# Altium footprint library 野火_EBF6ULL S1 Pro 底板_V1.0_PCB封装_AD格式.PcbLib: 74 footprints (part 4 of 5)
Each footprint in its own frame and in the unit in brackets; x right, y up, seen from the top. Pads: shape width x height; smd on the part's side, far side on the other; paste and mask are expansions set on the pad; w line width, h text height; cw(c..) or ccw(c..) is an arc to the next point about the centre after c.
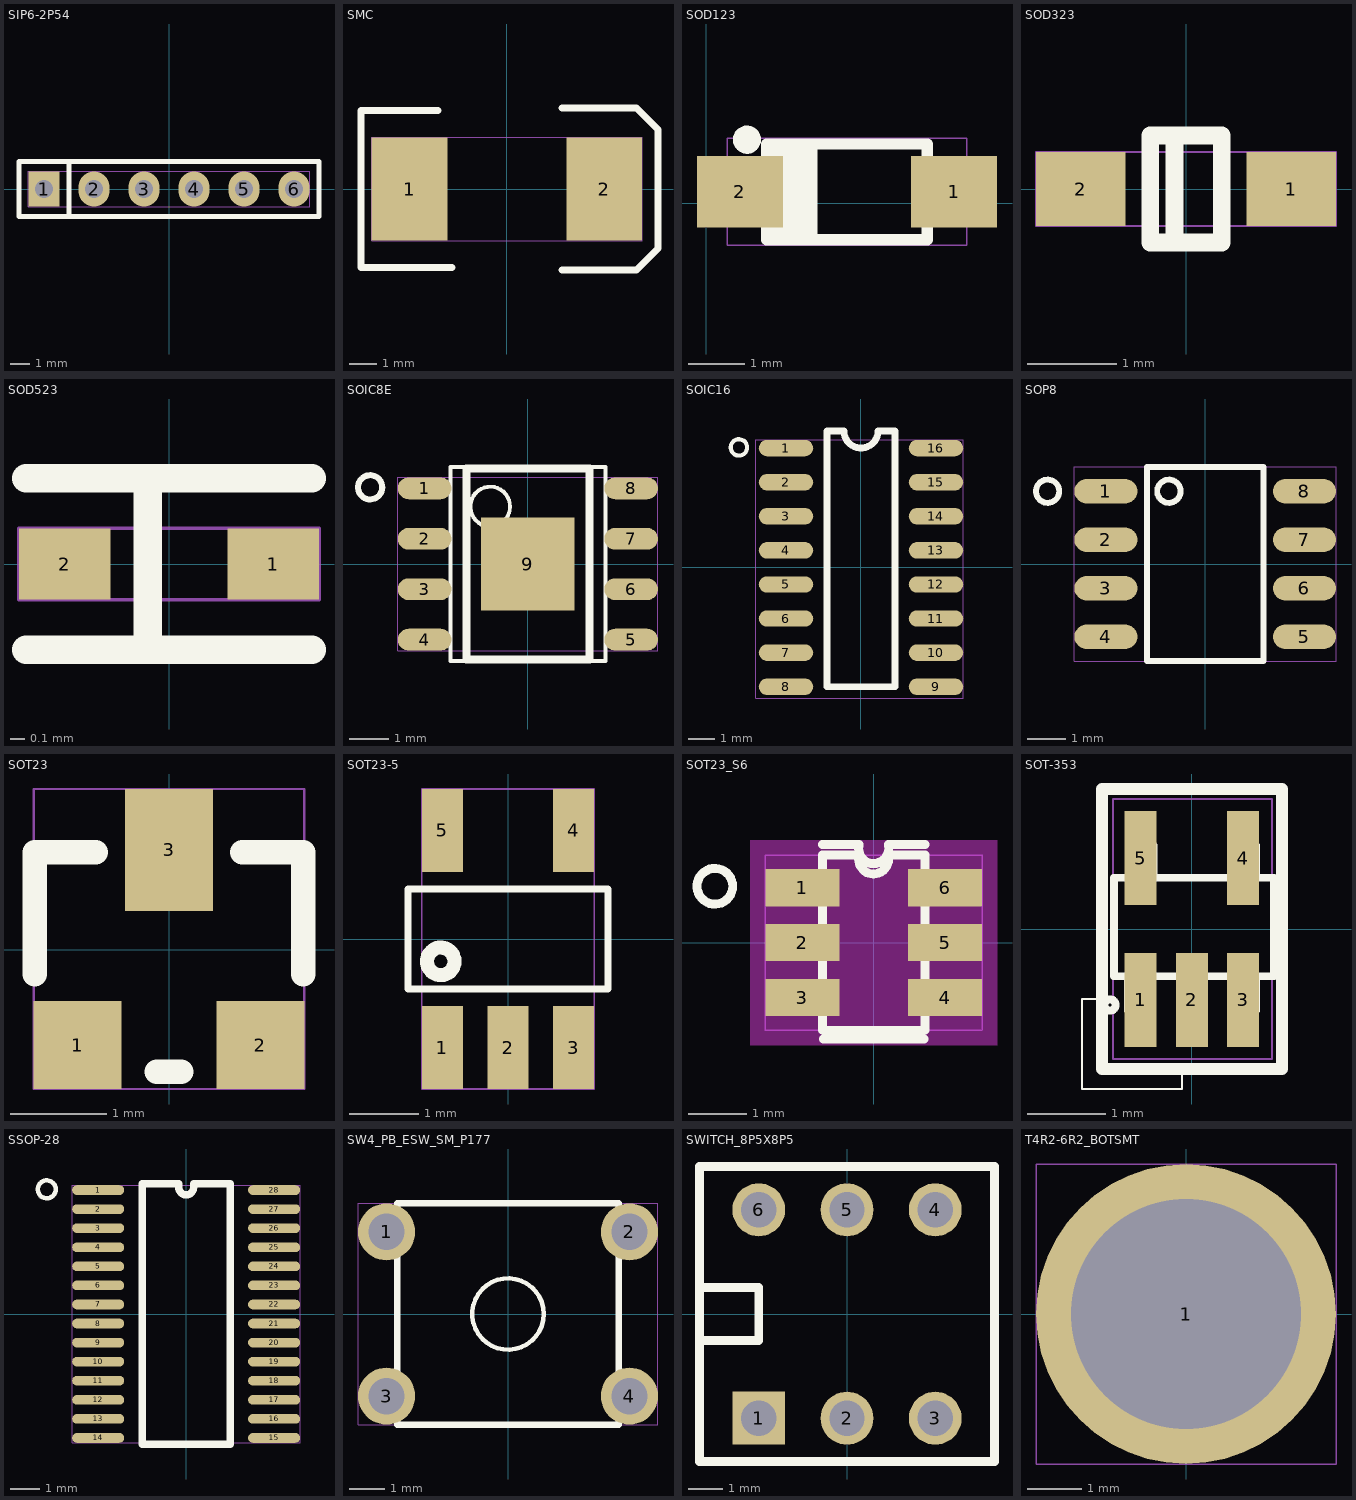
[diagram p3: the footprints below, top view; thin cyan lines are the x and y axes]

## SIP6-2P54 [mil]
pads (6):
  rect 62.99x70.87 hole 35.43 mask+1.97: 1(-250,0)
  oval 62.99x70.87 hole 35.43 mask+1.97: 2(-150,0) 3(-50,0) 4(50,0) 5(150,0) 6(250,0)
Top Overlay:
  lines w10: -200,-55.12 -200,55.12 ; -300,-55.12 -300,55.12 300,55.12 300,-55.12 -300,-55.12
Top Assembly:
  text "J15" at 53.33,25 h50
Mechanical 20:
  lines w1: -281.5,-35.43 -281.5,35.43 281.5,35.43 281.5,-35.43 -281.5,-35.43

## SMC [mil]
pads (2):
  rect 110.24x150 smd mask+1.97: 1(-141.73,0) 2(141.73,0)
Top Overlay:
  lines w10: -100,114.17 -212.6,114.17 -212.6,-114.17 -80,-114.17 ; 80,-118.11 188.5,-118.11 220,-86.61 220,86.61 188.5,118.11 80,118.11
Top Assembly:
  text "D3" at -38.93,-25 h50
Mechanical 20:
  lines w1: -196.85,-75 196.85,-75 196.85,75 -196.85,75 -196.85,-75

## SOD123 [mil]
height 53
pads (2):
  rect 60x50 smd mask+5: 1(173.23,7.87) 2(23.62,7.87)
Top Overlay:
  circle w9.84: c28.54,44.29 r4.92
  lines w7.87: 46.26,-25.59 46.26,41.34 ; 50.2,-25.59 50.2,41.34 ; 54.13,-25.59 54.13,41.34 ; 58.07,-25.59 58.07,41.34 ; 62.01,-25.59 62.01,41.34 ; 65.94,-25.59 65.94,41.34 ; 73.82,-25.59 73.82,41.34 ; 42.32,-25.59 42.32,41.34 ; 42.32,-25.59 154.53,-25.59 ; 42.32,-25.59 42.32,41.34 ; 42.32,-25.59 154.53,-25.59 ; 42.32,41.34 154.53,41.34 ; 42.32,41.34 154.53,41.34 ; 154.53,-25.59 154.53,41.34 ; 154.53,-25.59 154.53,41.34 ; 22.64,-0.98 22.64,16.73 38.39,16.73 38.39,-0.98 22.64,-0.98 ; 158.46,-0.98 158.46,16.73 174.21,16.73 174.21,-0.98 158.46,-0.98
Top Assembly:
  text "D12" at 57.25,25 h50
Mechanical 20:
  lines w1: 14.76,-29.53 182.09,-29.53 182.09,45.28 14.76,45.28 14.76,-29.53

## SOD323 [mm]
pads (2):
  rect 1x0.83 smd mask+0.05: 1(1.18,0) 2(-1.18,0)
Top Overlay:
  lines w0.2: -0.13,-0.6 -0.13,0.6 ; -0.4,-0.6 0.4,-0.6 0.4,0.6 -0.4,0.6 -0.4,-0.6
Top Assembly:
  text "Z5" at 0.989,0.635 h1.27
Mechanical 20:
  lines w0.025: -1.68,-0.415 1.68,-0.415 1.68,0.415 -1.68,0.415 -1.68,-0.415

## SOD523 [mm]
pads (2):
  rect 0.64x0.5 smd mask+0.05: 1(0.73,0) 2(-0.73,0)
Top Overlay:
  lines w0.2: -1,-0.6 1,-0.6 ; -1,0.6 1,0.6 ; -0.15,-0.575 -0.15,0.6
Top Assembly:
  text "TVS5" at -2.053,-0.635 h1.27
Mechanical 20:
  lines w0.025: -1.05,-0.25 1.05,-0.25 1.05,0.25 -1.05,0.25 -1.05,-0.25

## SOIC8E [mm]
pads (9):
  oval 1.35x0.55 smd mask+0.05: 1(-2.6,1.905) 2(-2.6,0.635) 3(-2.6,-0.635) 4(-2.6,-1.905) 5(2.6,-1.905) 6(2.6,-0.635) 7(2.6,0.635) 8(2.6,1.905)
  rect 2.35x2.35 smd mask+0.05: 9(0,0)
Top Overlay:
  circle w0.152: c-3.972,1.93 r0.305
  circle w0.1: c-0.95,1.445 r0.5
  lines w0.1: -1.95,-2.445 -1.95,2.445 1.95,2.445 1.95,-2.445 -1.95,-2.445
  lines w0.2: -1.55,-2.4 -1.55,2.4 1.55,2.4 1.55,-2.4 -1.55,-2.4
Top Assembly:
  text "U1" at 0.75,0.635 h1.27
Mechanical 20:
  lines w0.025: -3.275,-2.18 3.275,-2.18 3.275,2.18 -3.275,2.18 -3.275,-2.18

## SOIC16 [mil]
pads (16):
  oval 80x24 smd mask+2.5: 1(-110,175) 2(-110,125) 3(-110,75) 4(-110,25) 5(-110,-25) 6(-110,-75) 7(-110,-125) 8(-110,-175) 9(110,-175) 10(110,-125) 11(110,-75) 12(110,-25) 13(110,25) 14(110,75) 15(110,125) 16(110,175)
Top Overlay:
  circle w5.98: c-179.02,175.99 r12.02
  lines w10: -50,-175 -50,200 -25,200 ccw(c0,200) 25,200 50,200 50,-175 -50,-175
Top Assembly:
  text "U11" at -47.85,-25 h50
Mechanical 20:
  lines w1: -154,-192 150,-192 150,187 -154,187 -154,-192

## SOP8 [mil]
pads (8):
  oval 65x25 smd mask+1.97: 1(-102.36,75) 2(-102.36,25) 3(-102.36,-25) 4(-102.36,-75) 5(102.36,-75) 6(102.36,-25) 7(102.36,25) 8(102.36,75)
Top Overlay:
  circle w6: c-162.36,75 r12
  circle w6: c-37.36,75 r12
  lines w6: -60,-100 60,-100 60,100 -60,100 -60,-100
Top Assembly:
  text "U9" at 39.04,25 h50
Mechanical 20:
  lines w1: -134.86,-100 -134.86,100 134.86,100 134.86,-100 -134.86,-100

## SOT23 [mil]
pads (3):
  rect 36x36 smd mask+1.97: 1(-37.5,-39) 2(37.5,-39)
  rect 36x50 smd mask+1.97: 3(0,41)
Top Overlay:
  lines w10: -55,-10 -55,40 -30,40 ; -5,-50 5,-50 ; 30,40 55,40 55,-10
Top Assembly:
  text "U21" at -51.78,-25 h50
Mechanical 20:
  lines w1: -55.5,-57 55.5,-57 55.5,66 -55.5,66 -55.5,-57

## SOT23-5 [mil]
pads (5):
  rect 23.62x47.24 smd mask+1.97: 1(-37.4,-62.01) 2(0,-62.01) 3(37.4,-62.01) 4(37.4,62.01) 5(-37.4,62.01)
Top Overlay:
  circle w8: c-38.4,-12.79 r7.87
  lines w4: -57.09,-28.54 57.09,-28.54 57.09,18.7 57.09,28.54 -57.09,28.54 -57.09,18.7 -57.09,-28.54
Top Assembly:
  text "U3" at 40.23,25 h50
Mechanical 20:
  lines w1: -49.21,-85.63 49.21,-85.63 49.21,85.63 -49.21,85.63 -49.21,-85.63

## SOT23_S6 [mil]
height 57
pads (6):
  rect 50x25 smd mask+2: 1(-48,37) 2(-48,0) 3(-48,-37) 4(48,-37) 5(48,0) 6(48,37)
Top Layer keep-out:
  region: -83.06,-68.96 -83.06,68.98 83,68.98 83,-68.96
Top Overlay:
  circle w5.98: c-107.02,37.99 r12.02
  lines w6: -34.5,66 -10,66 ; -34,-65 34,-65 ; -10,58 ccw(c-0.21,56.22) -0.21,46.27 ccw(c-0.21,56.58) 10,58 9.79,58.27 ; -10,59 -34.5,59 -34.5,-59 34.5,-59 34.5,59 10,59 ; -10,65 ccw(c-0.21,63.22) -0.21,53.27 ccw(c-0.21,63.58) 10,65 9.79,65.27 ; 10,66 34.5,66
Top Assembly:
  text "U23" at -62.49,-25 h50
Mechanical 20:
  lines w1: -73,-58.96 -73,58.98 73,58.98 73,-58.96 -73,-58.96

## SOT-353 [mil]
height 43
pads (5):
  rect 16x47 smd mask+3: 1(-25.59,-35.43) 2(0,-35.43) 3(25.59,-35.43) 4(25.59,35.43) 5(-25.59,35.43)
Top Overlay:
  circle w3.94: c-41,-38 r2.83
  lines w1: -55,-80 -5,-80 -5,-70 -45,-70 -45,-35 -55,-35 -55,-80
  lines w3.94: -32,-24 -32,-40.83 -20,-40.83 ; -31.18,26 -31.18,40.83 ; -31.18,41.83 -19.18,41.83 -19.18,26 ; -20,-40 -20,-25 ; -6,-24 -6,-40.83 6,-40.83 ; 6,-40 6,-24 ; 20,-24 20,-40.83 32,-40.83 ; 20,26 20,41 ; 20,41.83 32,41.83 32,26 ; 32,-40 32,-24 ; -39,-23.61 -39,25.61 41,25.61 41,-23.61 -39,-23.61
  lines w6: -45,-70 -45,70 45,70 45,-70 -45,-70
Top Assembly:
  text "U27" at 62.49,25 h50
Mechanical 20:
  lines w1: -39.37,-65 -39.37,65 40,65 40,-65 -39.37,-65

## SSOP-28 [mil]
pads (28):
  oval 70x13 smd mask+2.5: 1(-118.11,166.4) 2(-118.11,140.8) 3(-118.11,115.2) 4(-118.11,89.6) 5(-118.11,64) 6(-118.11,38.4) 7(-118.11,12.8) 8(-118.11,-12.8) 9(-118.11,-38.4) 10(-118.11,-64) 11(-118.11,-89.6) 12(-118.11,-115.2) 13(-118.11,-140.8) 14(-118.11,-166.4) 15(118.11,-166.4) 16(118.11,-140.8) 17(118.11,-115.2) 18(118.11,-89.6) 19(118.11,-64) 20(118.11,-38.4) 21(118.11,-12.8) 22(118.11,12.8) 23(118.11,38.4) 24(118.11,64) 25(118.11,89.6) 26(118.11,115.2) 27(118.11,140.8) 28(118.11,166.4)
Top Overlay:
  circle w5.98: c-187.13,167.39 r12.02
  lines w10: -59.06,-175 59.06,-175 59.06,175 10,175 10,170 cw(c0,170) -10,170 -10,175 -59.06,175 -59.06,-175
Top Assembly:
  text "U17" at 58.56,25 h50
Mechanical 20:
  lines w1: -153.11,-172.9 153.11,-172.9 153.11,172.9 -153.11,172.9 -153.11,-172.9

## SW4_PB_ESW_SM_P177 [mil]
pads (4):
  round 63 hole 40 mask+2.5: 1(-133.86,90.55) 2(133.86,90.55) 3(-133.86,-90.55) 4(133.86,-90.55)
Top Overlay:
  circle w5: c0,0 r39.37
  lines w7: -122.05,-122.05 -122.05,122.05 122.05,122.05 122.05,-122.05 -122.05,-122.05
Top Assembly:
  text "SW4" at -68.92,-25 h50
Mechanical 20:
  lines w1: -165.35,-122.05 165.35,-122.05 165.35,122.05 -165.35,122.05 -165.35,-122.05

## SWITCH_8P5X8P5 [mil]
pads (6):
  rect 60x60 / inner round 60 / far side rect 60x60 hole 40 mask+2.5: 1(-100,-118.11)
  round 60 hole 40 mask+2.5: 2(0,-118.11) 3(100,-118.11) 4(100,118.11) 5(0,118.11) 6(-100,118.11)
Top Overlay:
  lines w10: -167.32,-30 -100,-30 -100,30 -167.32,30 ; -167.32,-167.32 -167.32,167.32 167.32,167.32 167.32,-167.32 -167.32,-167.32
Top Assembly:
  text "SW6" at -66.54,-25 h50
Mechanical 20:
  lines w1: -170,-170 -170,170 170,170 170,-170 -170,-170

## T4R2-6R2_BOTSMT [mil]
pads (1):
  round 216.54 / inner round 216.54 / far side round 244.09 hole 166.14 mask+1.97: 1(0,0)
Top Assembly:
  text "H9" at -39.04,-25 h50
Mechanical 20:
  lines w1: -108.27,-108.27 108.27,-108.27 108.27,108.27 -108.27,108.27 -108.27,-108.27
